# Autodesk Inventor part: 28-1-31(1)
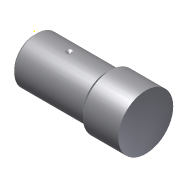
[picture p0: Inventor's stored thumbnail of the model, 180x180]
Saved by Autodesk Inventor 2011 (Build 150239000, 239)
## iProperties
Created: 2014-01
Part Number: 28-1-31(1)
Document SubType Name: Modeling
Designer: Administrator
Density: 1 g/cm^3
Author: Administrator
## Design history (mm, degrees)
sketch "草图1"
  geometry: L1 (0, 0)-(0, 9); L2 (0, 9)-(1.414, 10.414); L3 (1.414, 10.414)-(32.414, 10.414); L4 (32.414, 10.414)-(32.414, 8.414); L5 (32.414, 8.414)-(34.414, 8.414); L6 (34.414, 8.414)-(34.414, 12.414); L7 (34.414, 12.414)-(50.414, 12.414); L8 (50.414, 12.414)-(50.414, 0); L9 (50.414, 0)-(0, 0)
  constraints: 18 end point, 4 perpendicular, 3 parallel, 1 vertical
  dimensions: "d0" = 9 distance of L1.start L1.end; "d1" = 2 distance of L1.end L2.end; "d2" = 135 deg angle of L1 L2; "d3" = 31 distance of L2.end L3.end; "d4" = 2 distance of L3.end L4.end; "d5" = 2 distance of L4.end L5.end; "d6" = 4 distance of L5.end L6.end; "d7" = 16 distance of L6.end L7.end
revolve "旋转1" sketch "草图1" stored, may be unused: angle "d8" = 90 deg
node "工作平面2"
sketch "草图3"
  geometry: L1 (0, 9)-(0, -9) reference; L2 (-9, -2.5)-(-16, -2.5); L3 (-16, 2.5)-(-9, 2.5); L4 (-23, -2.5)-(-16, -2.5); L5 (-16, 2.5)-(-23, 2.5); A1 r 2.5 centre (-9, 0) between (-9, -2.5) and (-9, 2.5); A2 r 2.5 centre (-23, 0) between (-23, 2.5) and (-23, -2.5); 1 further point
  constraints: 8 end point, 4 point on circle, 2 centre point, 1 parallel, 1 perpendicular, 1 tangent
  dimensions: "d16" = 5 diameter of A1; "d17" = 7 distance of L2.start L2.end; "d18" = 9 distance from line of A1.centre L1
extrude "拉伸2" cut sketch "草图3" distance "d19" = 23; taper "d20" = 0 deg
node "工作平面3"
sketch "草图4"
  geometry: 2 further points
  dimensions: "d22" = 16 distance of point (0, 0) point (16, 0)
node "工作平面4"
sketch "草图5"
  geometry: 2 further points
hole "Hole1" sketch "草图5" at (16, 0) diameter "d24" = 3; stored, may be unused: countersink angle "d28" = 90 deg, drill point angle "d30" = 120 deg; dims "d25" = 6, "d26" = 4, "d27" = 2, "d29" = 1
sketch "草图6"
  geometry: 1 further point
node "实体1"
other parameters: "d21" = 10.414, "d23" = 1
